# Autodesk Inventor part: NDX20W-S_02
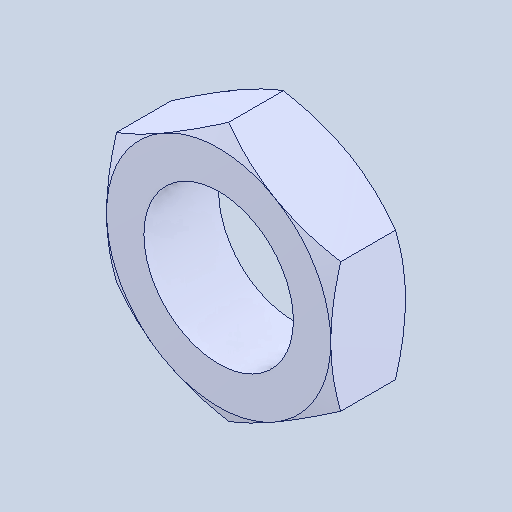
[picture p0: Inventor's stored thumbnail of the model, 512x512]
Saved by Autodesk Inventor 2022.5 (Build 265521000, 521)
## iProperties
Created: 2024-05
Part Number: NDX20W-S_02
Material: 一般
Document SubType Name: Modeling
Designer: ImaoCorp
Density: 1 g/cm^3
Appearance: 既定
Author: ImaoCorp
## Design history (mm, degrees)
feature "NDX20W-S_02"
node "ソリッド1"
